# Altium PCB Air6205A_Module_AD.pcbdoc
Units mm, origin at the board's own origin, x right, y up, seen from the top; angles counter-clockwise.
Board outline 26.31 x 26.35 mm, 2 copper layers (Top Layer, Bottom Layer); 1 components, 0 nets, 36 pads, 0 vias.
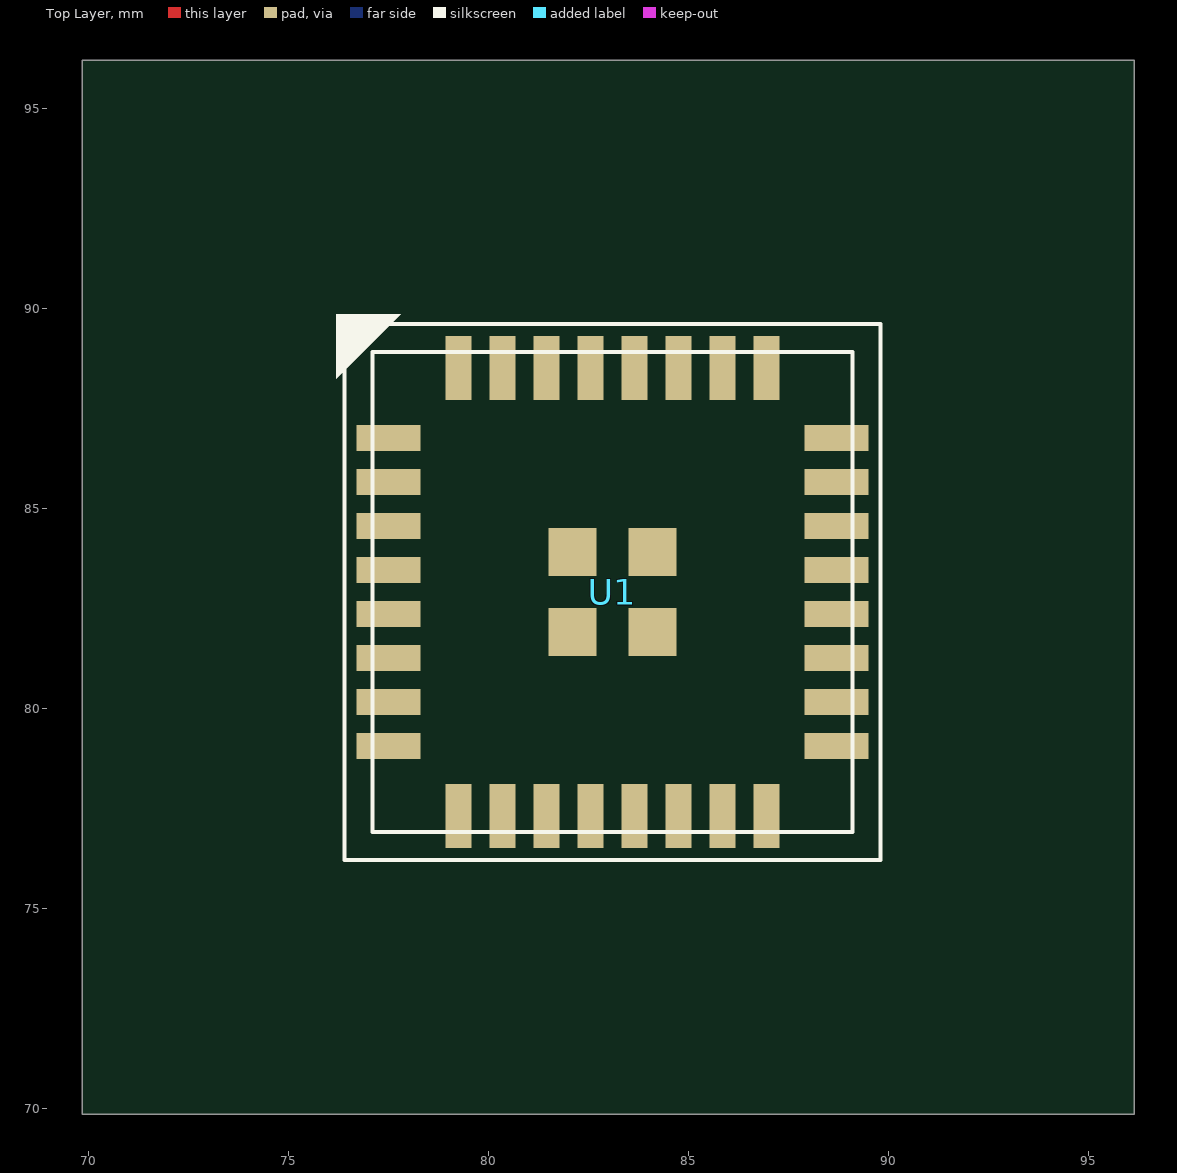
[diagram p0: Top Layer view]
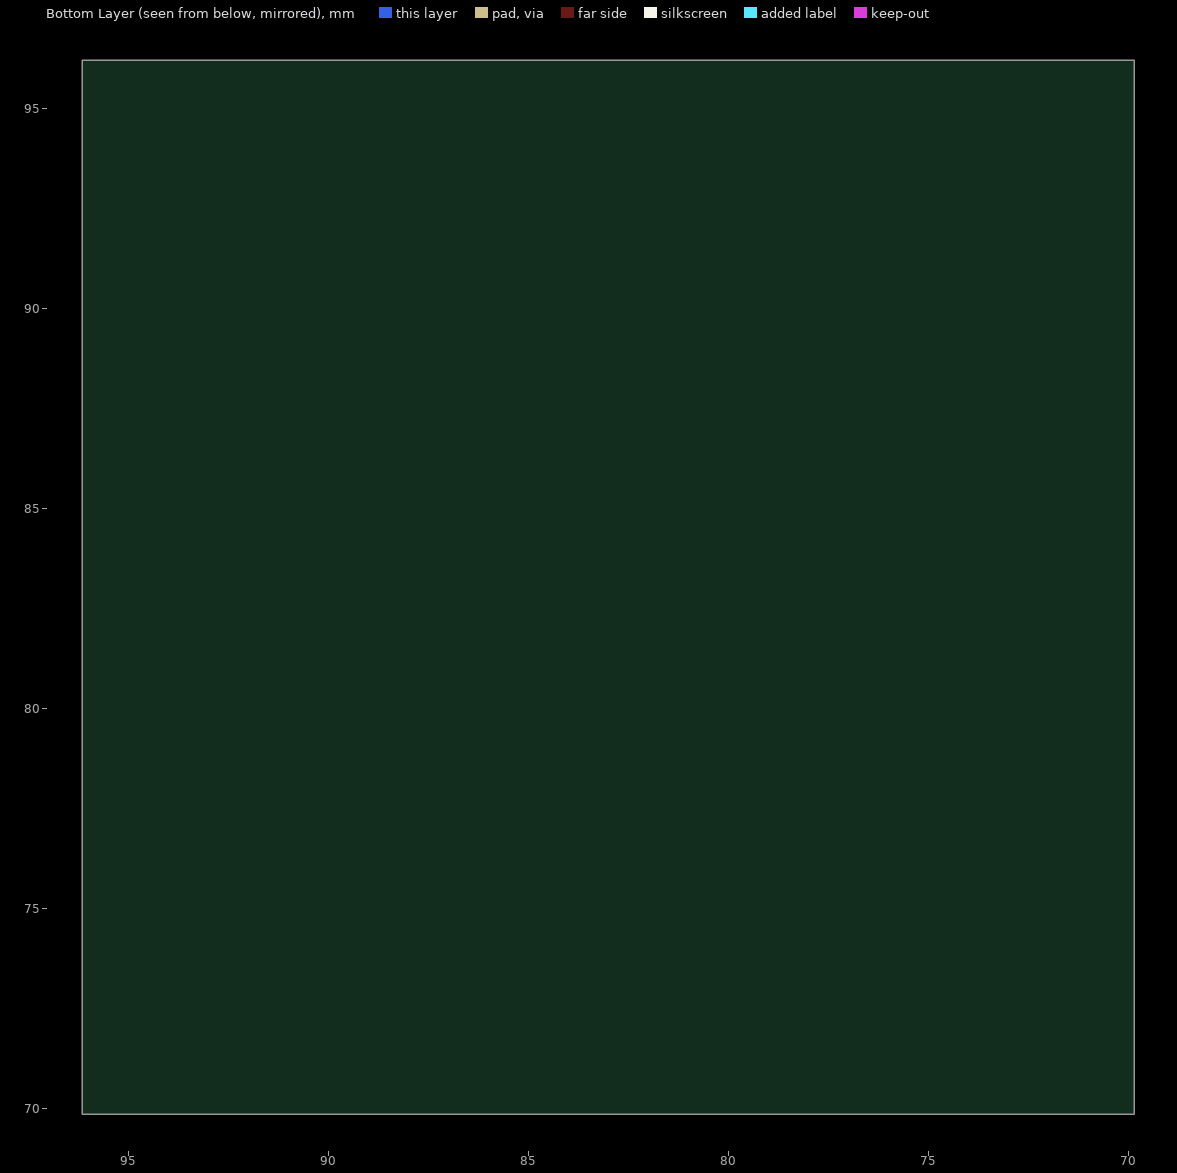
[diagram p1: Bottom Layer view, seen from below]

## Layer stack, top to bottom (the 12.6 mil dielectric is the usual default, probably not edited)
Top Layer: signal copper (thickness not stored)
Dielectric: dielectric 0.32, FR-4, Dk 4.8
Bottom Layer: signal copper (thickness not stored)

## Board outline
96.157,69.85 69.85,69.85 69.85,96.201 96.157,96.201

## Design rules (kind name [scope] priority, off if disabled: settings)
BoardOutlineClearance safeClearance [All] p0: genericclearance=0.254 ignorepadtopadclearanceinfootprint=FALSE except(0: Region-OutlineEdge Poly-OutlineEdge Text-OutlineEdge Sheet-OutlineEdge Hole-OutlineEdge Track-CutoutEdge SMDPad-CutoutEdge THPad-CutoutEdge Via-CutoutEdge Fill-CutoutEdge Region-CutoutEdge Poly-CutoutEdge Text-CutoutEdge Sheet-CutoutEdge Hole-CutoutEdge Arc-SplitContinuation Track-SplitContinuation SMDPad-SplitContinuation THPad-SplitContinuation Via-SplitContinuation Fill-SplitContinuation Poly-SplitContinuation Region-SplitContinuation Text-SplitContinuation; 0.152: Track-OutlineEdge SMDPad-OutlineEdge THPad-OutlineEdge Via-OutlineEdge Fill-OutlineEdge)
Clearance safeClearance [All] p1: gap=0.178 ignorepadtopadclearanceinfootprint=FALSE except(0: Region-Track Poly-Track Region-SMDPad Poly-SMDPad Region-THPad Poly-THPad Region-Via Poly-Via Region-Fill Poly-Fill Text-Fill Track-Region SMDPad-Region THPad-Region Via-Region Fill-Region Region-Region Poly-Region Text-Region Sheet-Region Hole-Region Track-Poly SMDPad-Poly THPad-Poly Via-Poly Fill-Poly Region-Poly Poly-Poly Text-Poly Sheet-Poly Hole-Poly Fill-Text Region-Text Poly-Text Text-Text Sheet-Text Hole-Text Region-Sheet Poly-Sheet Text-Sheet Sheet-Sheet Hole-Sheet Region-Hole Poly-Hole Text-Hole Sheet-Hole; 0.152: Track-Track SMDPad-Track THPad-Track Via-Track Fill-Track Text-Track Sheet-Track Hole-Track Track-SMDPad SMDPad-SMDPad THPad-SMDPad Via-SMDPad Fill-SMDPad Text-SMDPad Sheet-SMDPad Hole-SMDPad Track-THPad SMDPad-THPad THPad-THPad Via-THPad Fill-THPad Text-THPad Sheet-THPad Hole-THPad Track-Via SMDPad-Via THPad-Via Via-Via Fill-Via Text-Via Sheet-Via Hole-Via Track-Fill SMDPad-Fill THPad-Fill Via-Fill Fill-Fill Sheet-Fill Hole-Fill Track-Text SMDPad-Text THPad-Text Via-Text Track-Sheet SMDPad-Sheet THPad-Sheet Via-Sheet Fill-Sheet Track-Hole SMDPad-Hole THPad-Hole Via-Hole Fill-Hole Hole-Hole)
PasteMaskExpansion Common [All] p1: expansion=0
SolderMaskExpansion Common [All] p1: useseparateexpansions=TRUE expansion=0 expansionbottom=0
Width trackWidth [All] p1: maxlimit=12 minlimit=12 preferedwidth=12

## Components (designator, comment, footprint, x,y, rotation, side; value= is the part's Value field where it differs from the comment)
U1 "AIR6205A" AIR6205A-MODULE-PADS 83.107,82.9 r0 top

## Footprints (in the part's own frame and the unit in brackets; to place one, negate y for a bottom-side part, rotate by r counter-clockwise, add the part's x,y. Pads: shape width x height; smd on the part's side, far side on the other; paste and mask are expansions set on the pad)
AIR6205A-MODULE-PADS [mm]
  rect 1.6x0.65 smd: 1(-5.6,3.85) 2(-5.6,2.75) 3(-5.6,1.65) 4(-5.6,0.55) 5(-5.6,-0.55) 6(-5.6,-1.65) 7(-5.6,-2.75) 8(-5.6,-3.85) 17(5.6,-3.85) 18(5.6,-2.75) 19(5.6,-1.65) 20(5.6,-0.55) 21(5.6,0.55) 22(5.6,1.65) 23(5.6,2.75) 24(5.6,3.85)
  rect 0.65x1.6 smd: 9(-3.85,-5.6) 10(-2.75,-5.6) 11(-1.65,-5.6) 12(-0.55,-5.6) 13(0.55,-5.6) 14(1.65,-5.6) 15(2.75,-5.6) 16(3.85,-5.6) 25(3.85,5.6) 26(2.75,5.6) 27(1.65,5.6) 28(0.55,5.6) 29(-0.55,5.6) 30(-1.65,5.6) 31(-2.75,5.6) 32(-3.85,5.6)
  rect 1.2x1.2 smd: 33(-1,1) 34(-1,-1) 35(1,-1) 36(1,1)
  silkscreen extent -6.91,-6.7 6.7,6.95

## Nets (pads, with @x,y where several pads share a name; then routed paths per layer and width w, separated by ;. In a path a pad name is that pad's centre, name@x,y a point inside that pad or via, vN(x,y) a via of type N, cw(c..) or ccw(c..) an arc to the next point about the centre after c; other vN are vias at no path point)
pads on no net: U1.1 U1.2 U1.3 U1.4 U1.5 U1.6 U1.7 U1.8 U1.9 U1.10 U1.11 U1.12 U1.13 U1.14 U1.15 U1.16 U1.17 U1.18 U1.19 U1.20 U1.21 U1.22 U1.23 U1.24 U1.25 U1.26 U1.27 U1.28 U1.29 U1.30 U1.31 U1.32 U1.33 U1.34 U1.35 U1.36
